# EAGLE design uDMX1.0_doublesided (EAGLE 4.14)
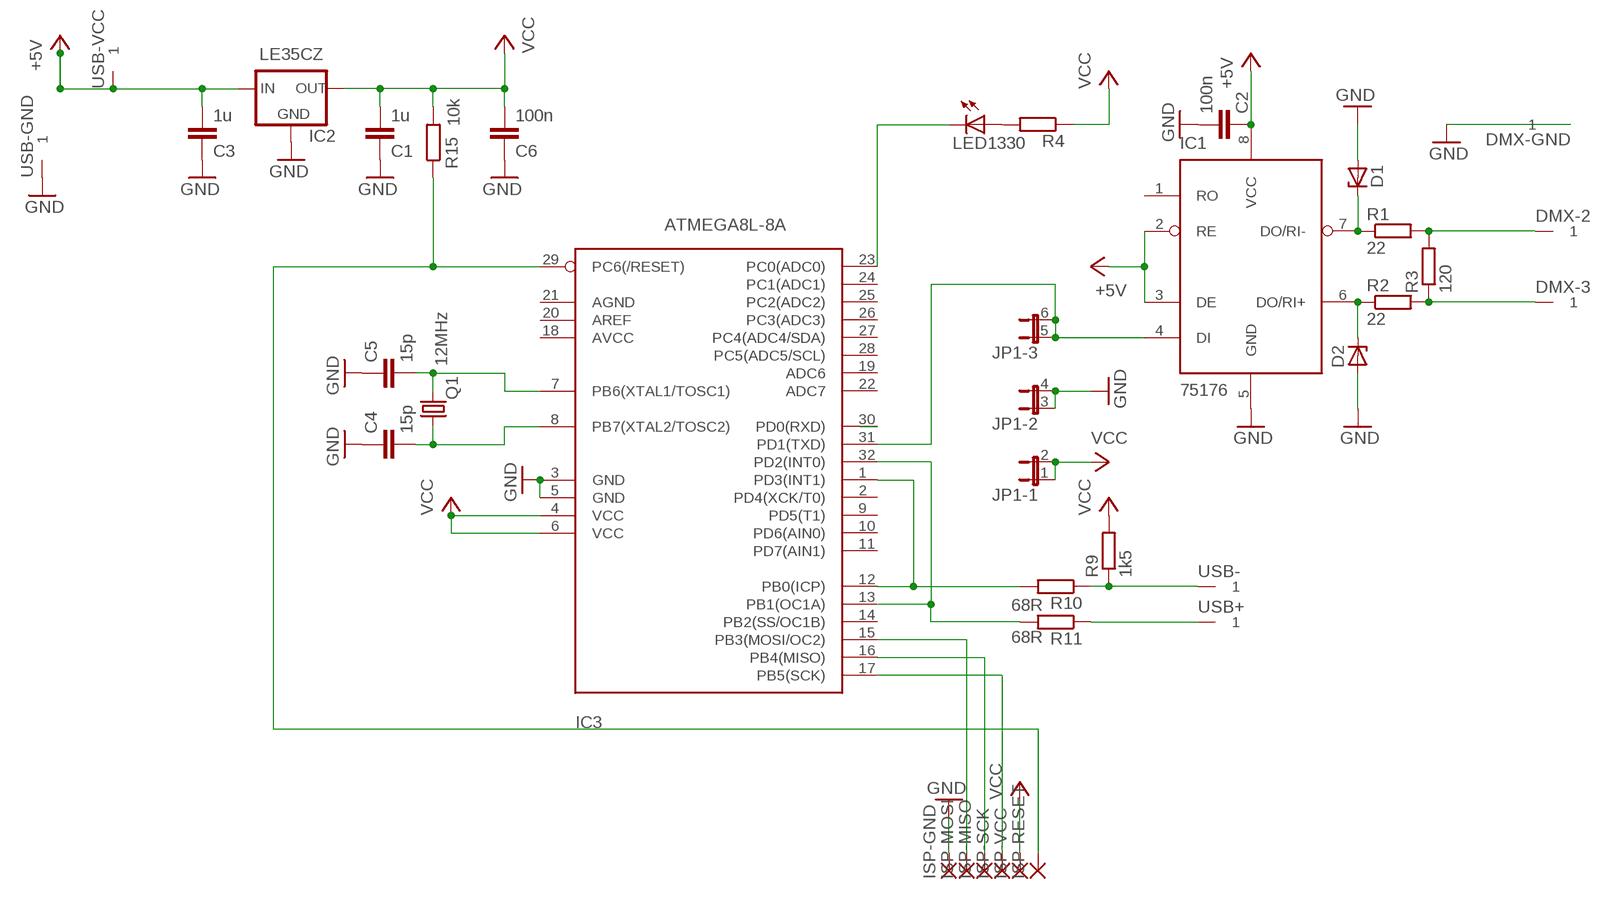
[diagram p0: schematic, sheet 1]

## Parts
C1  1u  C-EUC0603  [C0603]
C2  100n  C-EUC0603  [C0603]
C3  1u  C-EUC0603  [C0603]
C4  15p  C-EUC0805  [C0805]
C5  15p  C-EUC0805  [C0805]
C6  100n  C-EUC0603  [C0603]
D1  ZENER-DIODESOD80C  [SOD80C]
D2  ZENER-DIODESOD80C  [SOD80C]
DMX-2  ELLIPTICAL-PAD  [ELLIPTICAL]
DMX-3  ELLIPTICAL-PAD  [ELLIPTICAL]
DMX-GND  ELLIPTICAL-PAD  [ELLIPTICAL]
IC1  75176  [SO08]
IC2  LE35CZ  78LXX  [78LXX]
IC3  ATMEGA8L-8A  [TQFP32-08]
ISP-GND  SMD2  [SMD2]
ISP-MISO  SMD2  [SMD2]
ISP-MOSI  SMD2  [SMD2]
ISP-RESET  SMD2  [SMD2]
ISP-SCK  SMD2  [SMD2]
ISP-VCC  SMD2  [SMD2]
JP1  JP3QE  [JP3Q]
LED1  LEDCHIPLED_1206  [CHIPLED_1206]
Q1  12MHz  CRYTALHC49U-V  [HC49U-V]
R1  22  R-EU_M0805  [M0805]
R2  22  R-EU_M0805  [M0805]
R3  120  R-EU_M0805  [M0805]
R4  330  R-EU_M0805  [M0805]
R9  1k5  R-EU_M0805  [M0805]
R10  68R  R-EU_M0805  [M0805]
R11  68R  R-EU_M0805  [M0805]
R15  10k  R-EU_M0805  [M0805]
USB+  ELLIPTICAL-PAD  [ELLIPTICAL]
USB-  ELLIPTICAL-PAD  [ELLIPTICAL]
USB-GND  ELLIPTICAL-PAD  [ELLIPTICAL]
USB-VCC  ELLIPTICAL-PAD  [ELLIPTICAL]

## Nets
+5V: C2.1 C3.2 IC1.2(RE) IC1.3(DE) IC1.8(VCC) IC2.IN USB-VCC.A1
D-: R9.1 R10.1 USB-.A1
GND: C1.1 C2.2 C3.1 C4.1 C5.1 C6.1 D1.A D2.A DMX-GND.A1 IC1.5(GND) IC2.GND IC3.3(GND) IC3.5(GND) ISP-GND.1(P) JP1.3 JP1.4 USB-GND.A1
N$1: IC3.1(PD3(INT1)) IC3.12(PB0(ICP)) R10.2
N$2: IC3.30(PD0(RXD))
N$3: D1.C IC1.7(DO/RI-) R1.1
N$4: D2.C IC1.6(DO/RI+) R2.1
N$5: IC1.4(DI) IC3.31(PD1(TXD)) JP1.5 JP1.6
N$6: IC3.13(PB1(OC1A)) IC3.32(PD2(INT0)) R11.2
N$7: DMX-2.A1 R1.2 R3.2
N$8: DMX-3.A1 R2.2 R3.1
N$9: IC3.23(PC0(ADC0)) LED1.C
N$10: R11.1 USB+.A1
N$11: LED1.A R4.2
N$22: IC3.15(PB3(MOSI/OC2)) ISP-MOSI.1(P)
N$23: IC3.16(PB4(MISO)) ISP-MISO.1(P)
N$28: IC3.17(PB5(SCK)) ISP-SCK.1(P)
N$37: C4.2 IC3.8(PB7(XTAL2/TOSC2)) Q1.1
N$38: C5.2 IC3.7(PB6(XTAL1/TOSC1)) Q1.2
N$47: IC3.29(PC6(/RESET)) ISP-RESET.1(P) R15.1
VCC: C1.2 C6.2 IC2.OUT IC3.4(VCC) IC3.6(VCC) ISP-VCC.1(P) JP1.1 JP1.2 R4.1 R9.2 R15.2
Unconnected: IC1.1(RO) IC3.2(PD4(XCK/T0)) IC3.9(PD5(T1)) IC3.10(PD6(AIN0)) IC3.11(PD7(AIN1)) IC3.14(PB2(SS/OC1B)) IC3.18(AVCC) IC3.19(ADC6) IC3.20(AREF) IC3.21(AGND) IC3.22(ADC7) IC3.24(PC1(ADC1)) IC3.25(PC2(ADC2)) IC3.26(PC3(ADC3)) IC3.27(PC4(ADC4/SDA)) IC3.28(PC5(ADC5/SCL))

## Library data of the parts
C1-C6 = rcl:C-EU: CAPACITOR, European symbol
D1 D2 = diode:ZENER-DIODE: Z-Diode
DMX-2 DMX-3 DMX-GND USB+ USB- USB-GND USB-VCC = special-pad:ELLIPTICAL-PAD
IC1 = mexxlib:75176
IC2 = v-reg:78LXX: VOLTAGE REGULATOR
IC3 = avr:ATMEGA8: MICROCONTROLLER 8 Kbytes FLASH 1 kbytes SRAM 512 bytes EEPROM USART 6-channel 10 bit ADC 2-channel 8 bit ADC
ISP-GND ISP-MISO ISP-MOSI ISP-RESET ISP-SCK ISP-VCC = wirepad:SMD2: SMD PAD
JP1 = jumper:JP3QE: JUMPER
LED1 = led:LED: LED
Q1 = crystal:CRYTAL: CRYSTAL
R1-R4 R9-R11 R15 = rcl:R-EU_: RESISTOR, European symbol

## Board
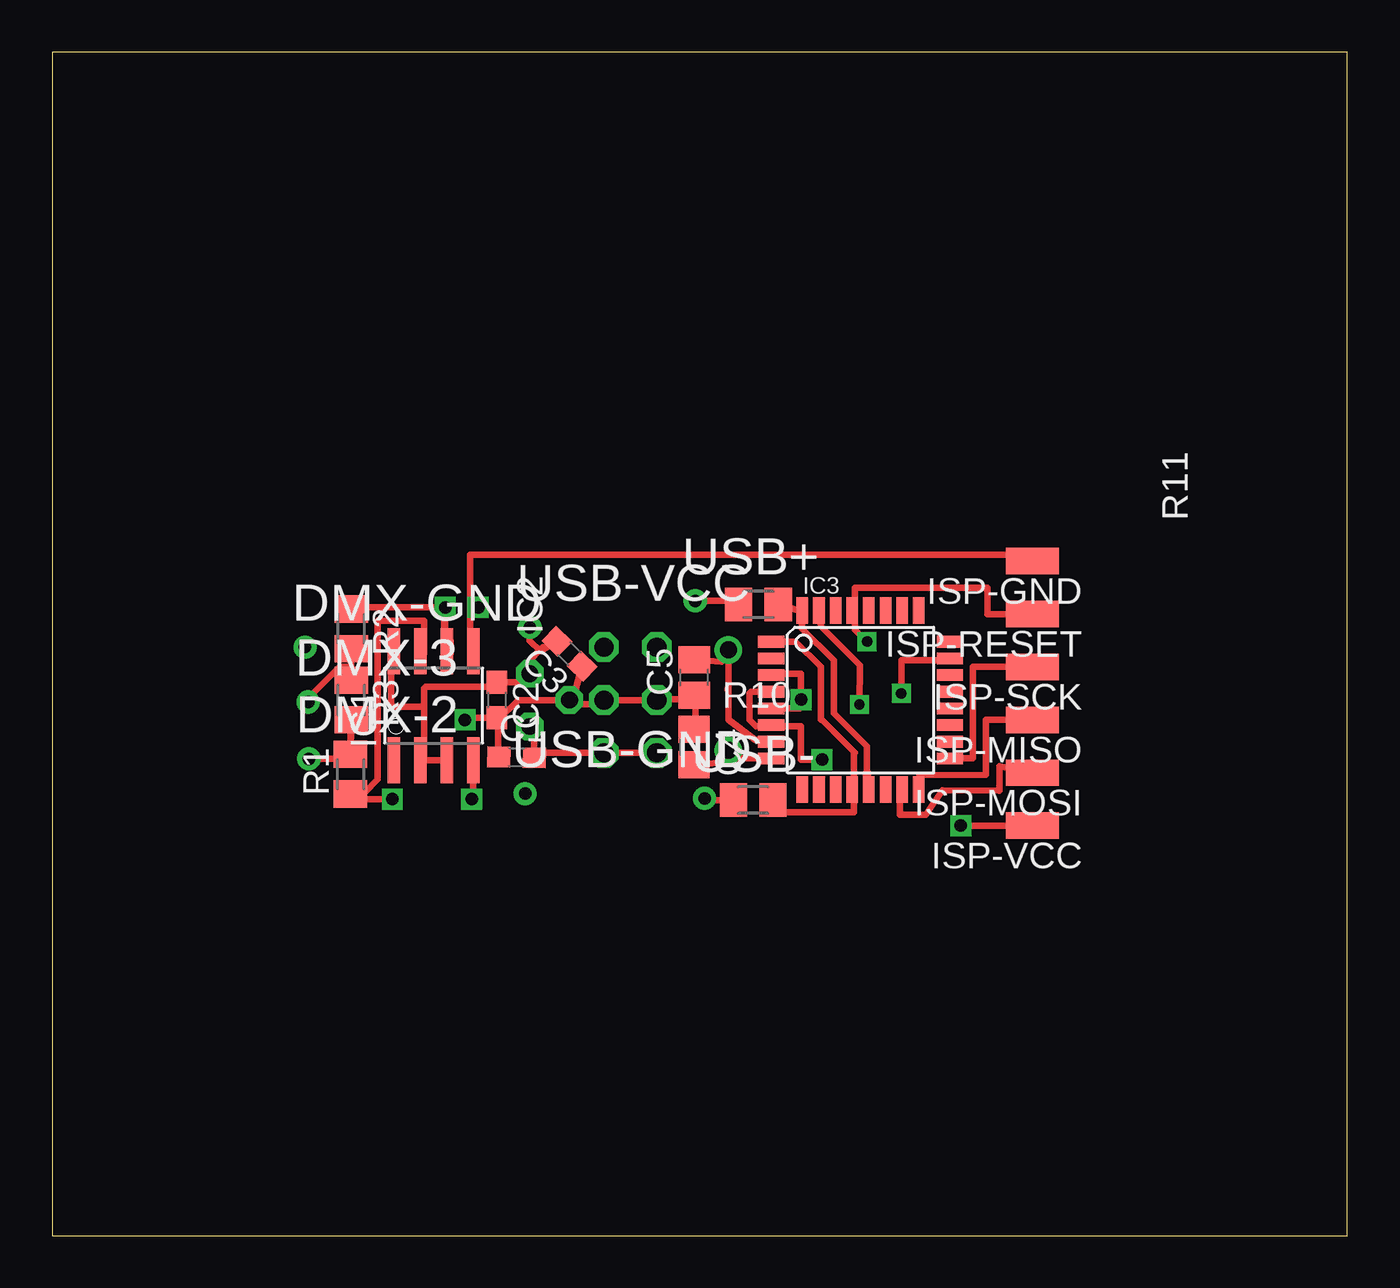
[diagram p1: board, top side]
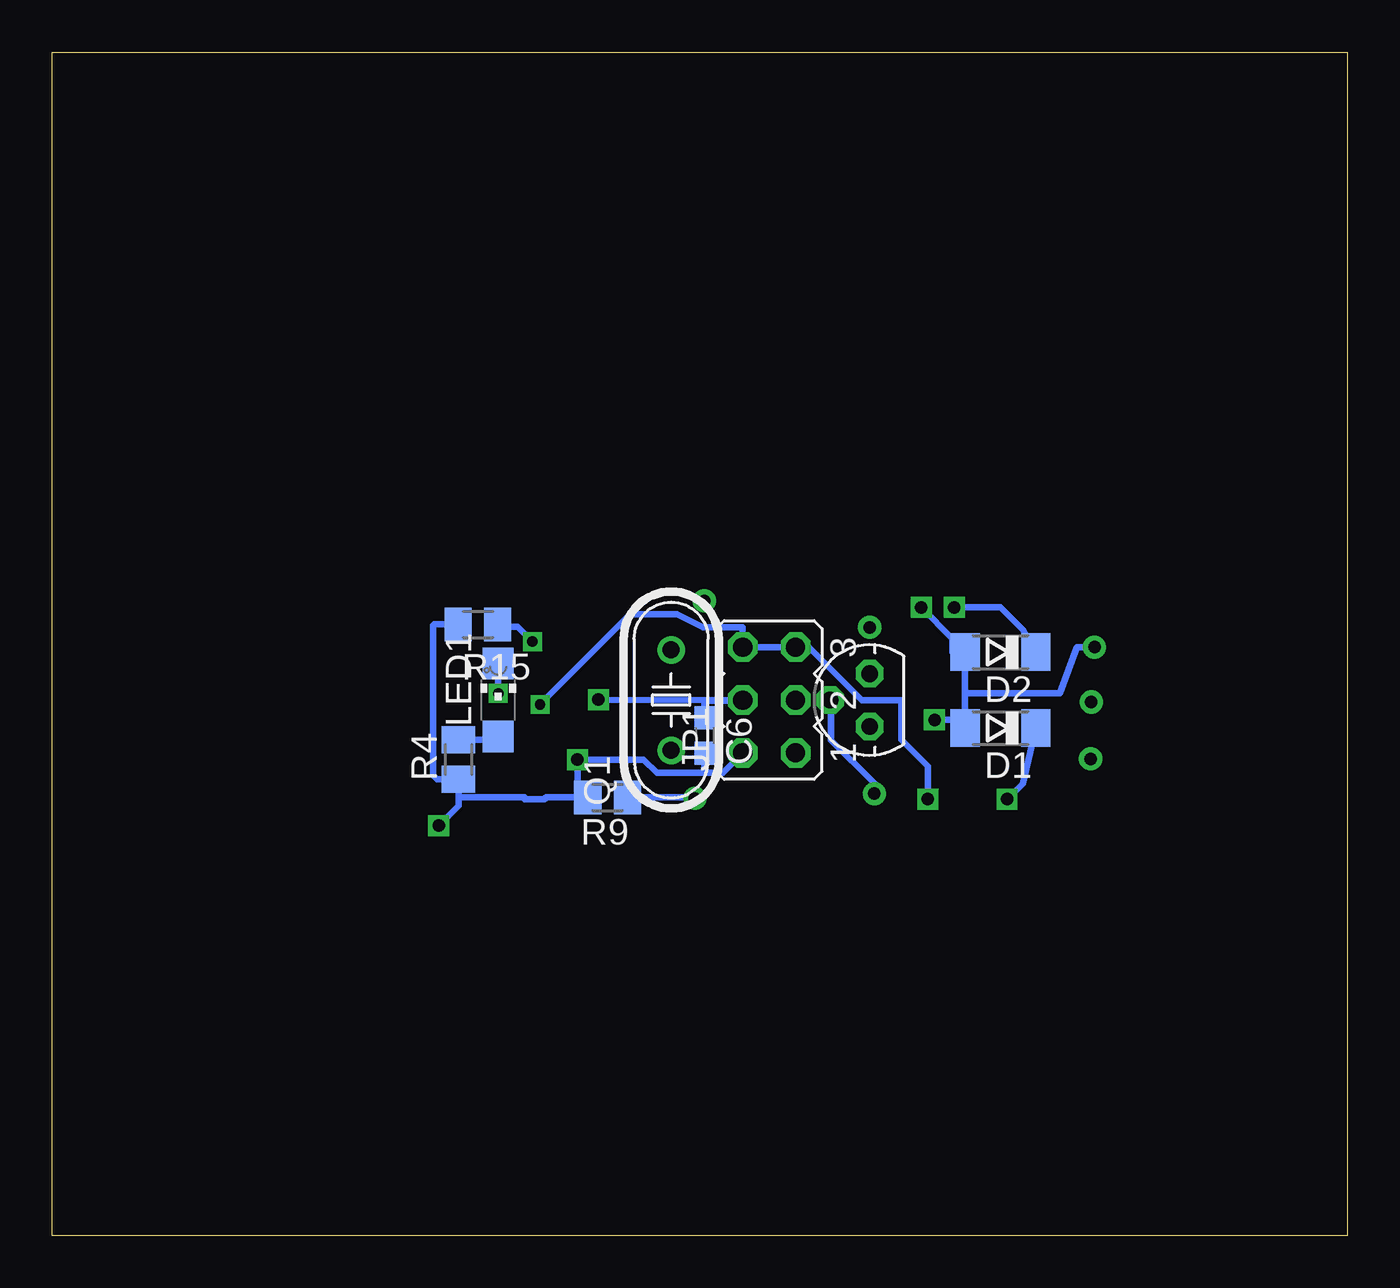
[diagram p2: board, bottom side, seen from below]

Size 62.22 x 56.82 mm. Coordinates in mm from the lower left corner, seen from the top.
Outline: 0,0 62.22,0 62.22,56.82 0,56.82 0,0
Copper layers (1*16): Top 0.035mm / dielectric 1.5mm / Bottom 0.035mm
Design rules "default": minimum track width 10mil, minimum drill 24mil, track to track 8mil, track to pad 8mil, pad to pad 8mil, via to via 8mil, smd to smd 8mil, copper to edge 40mil, drill to drill 8mil, minimum pad ring 10mil, minimum via ring 8mil, stop-mask expansion 4mil, vias tented up to drill 0mil, thermal gap 10mil

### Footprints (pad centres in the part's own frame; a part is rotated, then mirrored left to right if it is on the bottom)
C0603 = smd 1.1 x 1: 1 -0.85,0; 2 0.85,0
C0805 = smd 1.3 x 1.5: 1 -0.85,0; 2 0.85,0
SOD80C = smd 1.4 x 1.8: A 1.7,0; C -1.7,0
ELLIPTICAL = drill 0.6 round: A1 0,0
SO08 = smd 0.61 x 2.21: 1 -1.905,-2.616; 2 -0.635,-2.616; 3 0.635,-2.616; 4 1.905,-2.616; 5 1.905,2.616; 6 0.635,2.616; 7 -0.635,2.616; 8 -1.905,2.616
78LXX = drill 0.813 octagon: GND 0,1.905; IN 1.27,0; OUT -1.27,0
TQFP32-08 = smd 1.27 x 0.559: 1 -4.293,2.8; 2 -4.293,2; 3 -4.293,1.2; 4 -4.293,0.4; 5 -4.293,-0.4; 6 -4.293,-1.2; 7 -4.293,-2; 8 -4.293,-2.8; 17 4.293,-2.8; 18 4.293,-2; 19 4.293,-1.2; 20 4.293,-0.4; 21 4.293,0.4; 22 4.293,1.2; 23 4.293,2; 24 4.293,2.8 | smd 0.559 x 1.27: 9 -2.8,-4.293; 10 -2,-4.293; 11 -1.2,-4.293; 12 -0.4,-4.293; 13 0.4,-4.293; 14 1.2,-4.293; 15 2,-4.293; 16 2.8,-4.293; 25 2.8,4.293; 26 2,4.293; 27 1.2,4.293; 28 0.4,4.293; 29 -0.4,4.293; 30 -1.2,4.293; 31 -2,4.293; 32 -2.8,4.293
SMD2 = smd 1.27 x 2.54: 1 0,0
JP3Q = drill 0.914 octagon: 1 -2.54,-1.27; 2 -2.54,1.27; 3 0,-1.27; 4 0,1.27; 5 2.54,-1.27; 6 2.54,1.27
CHIPLED_1206 = smd 1.5 x 1.5: A 0,-1.75; C 0,1.75
HC49U-V = drill 0.813 round: 1 -2.413,0; 2 2.413,0
M0805 = smd 1.3 x 1.6: 1 -0.95,0; 2 0.95,0

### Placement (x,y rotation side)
C1  22.31,22.96 358.7 top
C2  21.36,25.71 270 top
C3  24.85,27.93 135.4 top
C4  30.83,23.46 270 top
C5  30.84,26.8 90 top
C6  30.87,24.01 270 bottom
D1  16.66,24.37 180 bottom
D2  16.66,28.01 180 bottom
DMX-2  12.34,22.89 0 top
DMX-3  12.3,25.62 0 top
DMX-GND  12.15,28.25 0 top
IC1  18.33,25.44 0 top
IC2  22.95,25.71 90 bottom
IC3  38.83,25.71 0 top
ISP-GND  47.09,32.38 90 top
ISP-MISO  47.09,24.76 90 top
ISP-MOSI  47.09,22.22 90 top
ISP-RESET  47.09,29.84 90 top
ISP-SCK  47.09,27.3 90 top
ISP-VCC  47.09,19.68 90 top
JP1  27.77,25.71 90 bottom
LED1  40.79,25.71 0 bottom
Q1  32.48,25.71 90 bottom
R1  14.33,22.15 90 top
R2  14.37,29.13 270 top
R3  14.37,25.71 270 top
R4  42.7,22.86 90 bottom
R9  35.54,21.03 180 bottom
R10  33.67,20.91 0 top
R11  33.93,30.3 0 top
R15  41.76,29.34 180 bottom
USB+  30.89,30.48 0 top
USB-  31.34,20.99 0 top
USB-GND  22.72,21.22 0 top
USB-VCC  22.95,29.21 0 top

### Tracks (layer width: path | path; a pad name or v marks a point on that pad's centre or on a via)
+5V
  Top 0.305: IC1.8 16.28,28.06 16.28,25.39 17.87,25.39 | 17.87,22.83 IC1.2 | 17.87,22.83 17.87,25.39 | IC1.3 17.87,22.83 | 23.47,28.14 23.58,28.25 | 23.47,28.14 C3.2 23.47,28.04 22.95,28.57 USB-VCC.A1 | 22.98,27.65 22.95,27.62 | 22.98,27.65 23.47,28.14 | 17.87,25.39 17.87,26.28 17.93,26.35 21.43,26.35 21.36,26.41 C2.1 22.59,26.56 23.01,26.98 IC2.IN 22.95,27.55 23.01,27.62 22.98,27.65 | 22.98,27.65
D-
  Top 0.305: USB-.A1 31.31,20.99 31.27,20.95 31.31,20.91 R10.1
  Bottom 0.305: 31.31,20.99 31.27,20.95 | USB-.A1 31.31,20.99 | R9.1 31.35,21.03 31.31,20.99
GND  (via drill 0.6)
  Top 0.305: IC3.5 35.92,25.31 35.97,25.39 | 35.97,25.39 35.97,26.98 34.39,26.98 34.39,26.91 IC3.3 | IC1.5 20.21,28.06 20.09,27.93 20.09,30.16 | 24.96,25.5 C3.1 | 24.96,25.5 IC2.GND 22.38,25.71 21.43,24.76 | ISP-GND.1 46.77,32.7 20.09,32.7 20.09,30.16 | C2.2 21.36,25.01 21.43,25.08 21.43,24.76 | 21.43,24.76 21.36,24.83 C2.2 | C2.2 19.94,24.86 v19.84,24.76 | v20.47,30.16 20.09,30.16 | C1.1 21.44,22.87 21.43,22.86 21.43,24.76 | 24.96,25.5 26.3,25.5 JP1.3 JP1.4 29.09,25.76 30.9,25.76 | 35.97,25.39 36.03,25.39 v35.97,25.73 | C4.1 30.95,24.13 30.9,24.17 30.9,25.76 | 30.9,25.76 30.95,25.71 | 30.9,25.76 C5.1
  Bottom 0.305: 18.96,28.01 18.88,27.93 18.36,27.82 18.36,26.03 | 18.96,28.01 D2.A | 18.36,26.03 D1.A 18.36,24.65 18.25,24.76 v19.84,24.76 | 18.36,26.03 13.81,26.03 12.99,28.25 DMX-GND.A1 | 18.96,28.01 18.96,28.65 v20.47,30.16 | 35.97,25.75 35.96,25.75 | 35.97,25.75 v35.97,25.73 JP1.4 29.16,25.71 29.25,25.62 29.49,25.68 30.89,25.68 30.92,25.68 30.86,25.65 30.87,25.64 C6.1 | 35.97,25.75 35.97,25.74 | USB-GND.A1 22.72,21.71 24.8,23.79 24.8,25.73 | 24.8,25.73 24.81,25.71 IC2.GND | 24.8,25.73 24.76,25.76
N$1
  Top 0.305: 38.51,21.27 38.51,21.42 IC3.12 38.43,21.35 | IC3.1 35.71,28.51 36.93,27.3 36.93,24.76 36.98,24.76 38.57,23.17 38.51,23.17 38.51,21.27 | 38.43,21.35 38.51,21.27 | 38.43,21.35 38.51,21.35 38.51,20.32 34.93,20.32 34.53,20.65 R10.2
N$3  (via drill 0.6)
  Top 0.305: IC1.7 17.74,28.06 17.87,27.93 17.87,29.52 15.64,29.52 15.64,21.9 15.01,21.27 R1.1 14.44,21.59 15.08,20.95 v16.34,20.95
  Bottom 0.305: D1.C 15.6,21.7 v16.34,20.95
N$4  (via drill 0.6)
  Top 0.305: 19.14,27.93 18.96,27.93 IC1.6 | 18.96,28.25 19.14,28.57 19.14,28.25 18.96,28.25 | IC1.6 18.96,28.25 | 18.96,28.25 18.82,28.25 | R2.1 14.38,30.16 14.69,29.84 | R2.1 14.69,29.84 | IC1.6 18.94,28.06 18.82,27.93 18.82,29.52 18.82,30.16 15.01,30.16 14.76,30.16 14.44,29.84 R2.1 | IC1.6 18.96,28.01 18.88,27.93 v18.88,30.16
  Bottom 0.305: D2.C 15.6,29.09 16.66,30.16 v18.88,30.16
N$5  (via drill 0.5, 0.6)
  Top 0.305: 36.93,30.16 36.83,30.06 IC3.31 36.77,29.86 36.82,29.54 36.98,29.21 38.8,27.39 v38.78,25.5 | 20.09,22.86 20.12,22.83 IC1.4 20.23,21.03 v20.15,20.95
  Bottom 0.305: v20.15,20.95 20.15,22.54 21.43,23.81 21.43,25.71 23.33,25.71 25.87,28.25 JP1.5 JP1.6 29.05,29.21 30.95,29.21 32.21,29.83 34.45,29.83 v38.78,25.5
N$6
  Top 0.305: 39.15,22.22 39.15,23.49 37.56,25.08 37.56,27.62 36.03,29.14 IC3.32 35.97,30 | 35.97,30 35.97,30.16 | R11.2 35.97,29.98 35.97,30
  Top 0.406: IC3.13 39.23,21.82 39.15,21.9 39.15,22.22 | 36.03,29.9 35.97,29.84 35.97,29.52 36.03,29.58 IC3.32 36.03,29.9
N$7
  Top 0.305: DMX-2.A1 12.57,22.89 14.33,22.89 R3.2 14.37,24.83 14.37,24.84 14.33,24.8 R1.2
N$8
  Top 0.305: 14.37,27.3 R3.1 | 14.37,27.3 R2.2 | DMX-3.A1 12.3,25.79 13.81,27.3 14.37,27.3
N$9  (via drill 0.5)
  Top 0.305: v40.79,26.03 40.79,27.62 43.33,27.62 43.33,27.71 IC3.23
  Bottom 0.305: LED1.C v40.79,26.03
N$10
  Top 0.305: 32.8,30.3 32.8,30.16 | 32.8,30.3 R11.1 | USB+.A1 32.8,30.48 32.8,30.3
N$11
  Bottom 0.305: R4.2 40.79,23.81 LED1.A
N$22
  Top 0.305: IC3.15 40.74,21.42 40.72,20.21 41.97,20.21 42.76,21.37 45.51,21.35 45.5,22.22 45.5,22.54 ISP-MOSI.1
N$23
  Top 0.305: IC3.16 41.63,21.32 41.67,22.11 44.85,22.12 44.85,24.76 44.86,24.76 | 44.86,24.76 | 44.86,24.76 ISP-MISO.1
N$28
  Top 0.305: IC3.17 43.28,22.91 | 43.28,22.91 43.59,22.91 | 43.28,22.91 44.23,22.91 44.23,27.3 ISP-SCK.1
N$37
  Top 0.305: IC3.8 33.06,22.91 32.48,22.86 Q1.1 32.48,23.23 32.54,23.17 32.06,22.7 C4.2
N$38
  Top 0.305: IC3.7 34.48,23.71 34.39,23.81 33.75,23.81 32.48,24.76 32.48,26.33 32.45,26.22 32.48,26.4 Q1.2 32.48,27.99 32.54,27.93 32.16,27.56 C5.2
N$47  (via drill 0.5)
  Top 0.305: IC3.29 38.57,30 | 38.57,30 38.57,31.11 44.92,31.11 44.92,29.84 ISP-RESET.1 47.14,29.84 | 38.57,30 38.57,29.09 v39.15,28.52
  Bottom 0.305: v39.15,28.52 | v39.15,28.52 39.87,29.24 40.74,29.24 40.81,29.31 R15.1
VCC  (via drill 0.6)
  Top 0.305: 34.44,24.44 35.97,24.44 35.97,22.86 v36.98,22.86 | 34.44,24.44 34.39,24.44 34.46,24.51 IC3.6 34.51,24.51 34.44,24.44 | 23.26,24.13 IC2.OUT 22.95,24.19 23.16,23.98 C1.2 23.16,23.02 23.01,23.17 JP1.1 JP1.2 | 47.14,19.68 ISP-VCC.1 v43.65,19.68 | IC3.4 33.57,26.11 33.49,26.03 33.49,24.76 33.81,24.44 34.44,24.44
  Bottom 0.305: R4.1 | 42.7,20.95 42.7,20.63 v43.65,19.68 | 42.7,20.95 R4.1 | 36.98,21.03 R9.2 | JP1.2 30,22.22 30.92,22.22 | 30.92,22.22 33.17,22.22 33.81,22.86 v36.98,22.86 36.98,21.03 | 36.98,21.03 36.98,20.95 | 36.98,21.03 38.49,21.03 38.57,20.95 39.53,20.95 39.61,21.03 39.61,21.05 | 39.61,21.05 39.52,21.05 39.52,20.95 | 39.61,21.05 42.59,21.05 42.7,20.95 | 30.92,22.22 30.92,22.21 30.87,22.26 C6.2 | R15.2 43.87,29.34 43.9,29.3 43.9,22.09 43.73,21.91 42.77,21.91 42.7,21.98 | 42.68,22 42.7,21.98 | 42.7,21.98 R4.1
